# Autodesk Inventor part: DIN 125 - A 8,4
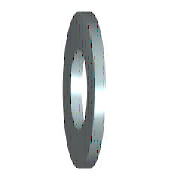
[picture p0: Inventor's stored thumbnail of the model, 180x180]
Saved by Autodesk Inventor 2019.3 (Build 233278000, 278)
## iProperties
Created: 2018-01
Part Number: DIN 125 - A 8,4
Material: Ocel, měkká
Description: Podložka
Document SubType Name: Modeling
Standard: DIN 125
Designer: B-hon
Standards Organization: DIN
Language: cs-CZ
Size Designation: A 8,4
Categories: <MemberInstance><Categories><Category DisplayName="Spojovací materiál" InternalName="e4da775c-781d-43d5-af7c-5136215cf5a6" Mnemonic="FSTN"><Category DisplayName
Density: 7.85 g/cm^3
Appearance: Pololeštěná
IsCustomPart: 0
Author: B-hon
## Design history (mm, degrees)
sketch "Náčrt"
  geometry: C1 r 8 at (0, 0); C2 r 4.2 at (0, 0); 1 further point
  constraints: 2 centre point, 2 coincident
  dimensions: "d0" = 8.4 diameter of C2 (= SD1); "d1" = 16 diameter of C1 (= SD2)
extrude "Těleso" new body sketch "Náčrt" distance "d2" = 1.6 (= SD); taper "d3" = 0 deg
workaxis "Work Axis1"
workplane "Work Plane1"
body "Solid1"
other parameters: "SD1" = 8.4 [user parameter; used in 1 equation term], "SD2" = 16 [user parameter; used in 1 equation term], "SD" = 1.6 [user parameter; used in 1 equation term], "d4" = 0, "d5" = 0, "d6" = 0, "d7" = 0, "NND" = 8 [user parameter]
